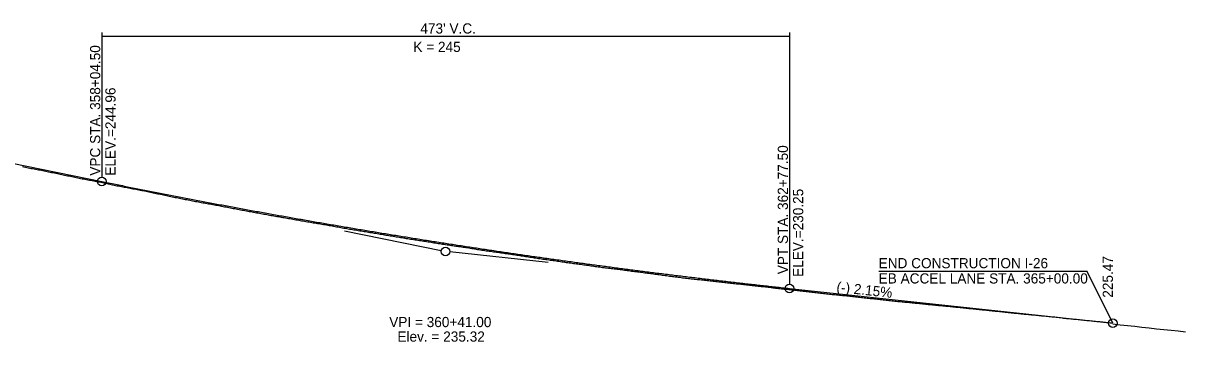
# Model space of a CAD drawing. Extents: x 69 to 2003113, y 512 to 837401.
# Drawn here: x 1914114 to 1914912, y 828577 to 828797 of the extents above; entities that cross this region are included whole.
import ezdxf

# ---------------------------------------------------------------- set-up
doc = ezdxf.new("R2010")
doc.units = 0
for name, color, linetype in [('BR_CENTER LINE BASELINE', 7, 'Continuous'), ('BR_CONCRETE', 7, 'Continuous'), ('BR_GRID DOTS', 7, 'Continuous'), ('BR_GRID LINES', 7, 'Continuous'), ('BR_TEXT', 7, 'Continuous'), ('RD_SHT_IplotShp', 7, 'Continuous')]:
    doc.layers.add(name, color=color, linetype=linetype)

msp = doc.modelspace()

# ---------------------------------------------------------------- linework, layer by layer
at = {"layer": 'BR_CENTER LINE BASELINE'}
for p, q in [((1914334.51, 828653.6), (1914401.14, 828640.02)), ((1914474.68, 828631.84), (1914407.06, 828639.1))]:
    msp.add_line(p, q, dxfattribs=at)
for centre in [(1914404.08, 828639.42), (1914863.08, 828590.15)]:
    msp.add_circle(centre, 3, dxfattribs=at)
at = {"layer": 'BR_GRID DOTS'}
for p, q in [((1914167.58, 828790.11), (1914167.58, 828690.61)), ((1914167.58, 828787.61), (1914640.58, 828787.61)), ((1914640.58, 828790.11), (1914640.58, 828617.03))]:
    msp.add_line(p, q, dxfattribs=at)
msp.add_lwpolyline([(1914863.08, 828590.15), (1914845.48, 828625.75), (1914701.98, 828625.75)], dxfattribs=at)
for centre in [(1914167.58, 828687.61), (1914640.58, 828614.03)]:
    msp.add_circle(centre, 3, dxfattribs=at)
at = {"layer": 'BR_GRID LINES'}
for p, q in [((1913864.58, 828749.35), (1914167.58, 828687.61)), ((1914640.58, 828614.03), (1914863.08, 828590.15))]:
    msp.add_line(p, q, dxfattribs=at)
msp.add_spline([(1914167.58, 828687.61), (1914177.04, 828685.69), (1914186.5, 828683.79), (1914195.96, 828681.91), (1914205.42, 828680.05), (1914214.88, 828678.2), (1914224.34, 828676.37), (1914233.8, 828674.56), (1914243.26, 828672.77), (1914252.72, 828671), (1914262.18, 828669.25), (1914271.64, 828667.51), (1914281.1, 828665.79), (1914290.56, 828664.09), (1914300.02, 828662.41), (1914309.48, 828660.75), (1914318.94, 828659.1), (1914328.4, 828657.48), (1914337.86, 828655.87), (1914347.32, 828654.28), (1914356.78, 828652.71), (1914366.24, 828651.15), (1914375.7, 828649.62), (1914385.16, 828648.1), (1914394.62, 828646.6), (1914404.08, 828645.12), (1914413.54, 828643.66), (1914423, 828642.21), (1914432.46, 828640.79), (1914441.92, 828639.38), (1914451.38, 828637.99), (1914460.84, 828636.62), (1914470.3, 828635.27), (1914479.76, 828633.93), (1914489.22, 828632.62), (1914498.68, 828631.32), (1914508.14, 828630.04), (1914517.6, 828628.78), (1914527.06, 828627.53), (1914536.52, 828626.31), (1914545.98, 828625.1), (1914555.44, 828623.91), (1914564.9, 828622.74), (1914574.36, 828621.59), (1914583.82, 828620.45), (1914593.28, 828619.34), (1914602.74, 828618.24), (1914612.2, 828617.16), (1914621.66, 828616.1), (1914631.12, 828615.06), (1914640.58, 828614.03)], degree=3, dxfattribs=at)
at = {"layer": 'BR_TEXT'}
for points in [[(1914113.08, 828697.81), (1914114.08, 828697.61), (1914115.08, 828697.42), (1914116.08, 828697.23), (1914117.08, 828697.04), (1914118.08, 828696.85), (1914119.08, 828696.66), (1914120.08, 828696.47), (1914121.08, 828696.28), (1914122.08, 828696.09), (1914123.08, 828695.9), (1914124.08, 828695.71), (1914125.08, 828695.52), (1914126.08, 828695.33), (1914127.08, 828695.13), (1914128.08, 828694.93), (1914129.08, 828694.72), (1914130.08, 828694.51), (1914131.08, 828694.31), (1914132.08, 828694.1), (1914133.08, 828693.9), (1914134.08, 828693.69), (1914135.08, 828693.49), (1914136.08, 828693.28), (1914137.08, 828693.07), (1914138.08, 828692.87), (1914139.08, 828692.66), (1914140.08, 828692.45), (1914141.08, 828692.24), (1914142.08, 828692.02), (1914143.08, 828691.81), (1914144.08, 828691.6), (1914145.08, 828691.39), (1914146.08, 828691.18), (1914147.08, 828690.97), (1914148.08, 828690.76), (1914149.08, 828690.54), (1914150.08, 828690.33), (1914151.08, 828690.12), (1914152.08, 828689.92), (1914153.08, 828689.74), (1914154.08, 828689.55), (1914155.08, 828689.36), (1914156.08, 828689.18), (1914157.08, 828688.99), (1914158.08, 828688.8), (1914159.08, 828688.62), (1914160.08, 828688.43), (1914161.08, 828688.25), (1914162.08, 828688.06), (1914163.08, 828687.87)], [(1914163.08, 828687.87), (1914164.08, 828687.68), (1914165.08, 828687.47), (1914166.08, 828687.26), (1914167.08, 828687.04), (1914168.08, 828686.83), (1914169.08, 828686.61), (1914170.08, 828686.4), (1914171.08, 828686.19), (1914172.08, 828685.97), (1914173.08, 828685.76), (1914174.08, 828685.54), (1914175.08, 828685.33), (1914176.08, 828685.12), (1914177.08, 828684.91), (1914178.08, 828684.73), (1914179.08, 828684.54), (1914180.08, 828684.35), (1914181.08, 828684.17), (1914182.08, 828683.98), (1914183.08, 828683.79), (1914184.08, 828683.61), (1914185.08, 828683.42), (1914186.08, 828683.23), (1914187.08, 828683.05), (1914188.08, 828682.86), (1914189.08, 828682.67), (1914190.08, 828682.48), (1914191.08, 828682.29), (1914192.08, 828682.09), (1914193.08, 828681.89), (1914194.08, 828681.7), (1914195.08, 828681.5), (1914196.08, 828681.3), (1914197.08, 828681.11), (1914198.08, 828680.91), (1914199.08, 828680.71), (1914200.08, 828680.52), (1914201.08, 828680.3), (1914202.08, 828680.09), (1914203.08, 828679.87), (1914204.08, 828679.66), (1914205.08, 828679.45), (1914206.08, 828679.23), (1914207.08, 828679.02), (1914208.08, 828678.81), (1914209.08, 828678.6), (1914210.08, 828678.39), (1914211.08, 828678.18), (1914212.08, 828677.97), (1914213.08, 828677.76), (1914214.08, 828677.55), (1914215.08, 828677.34), (1914216.08, 828677.13), (1914217.08, 828676.92), (1914218.08, 828676.71), (1914219.08, 828676.5), (1914220.08, 828676.29), (1914221.08, 828676.1), (1914222.08, 828675.92), (1914223.08, 828675.72), (1914224.08, 828675.52), (1914225.08, 828675.33), (1914226.08, 828675.13), (1914227.08, 828674.93), (1914228.08, 828674.74), (1914229.08, 828674.54), (1914230.08, 828674.35), (1914231.08, 828674.15), (1914232.08, 828673.95), (1914233.08, 828673.75), (1914234.08, 828673.56), (1914235.08, 828673.38), (1914236.08, 828673.21), (1914237.08, 828673.03), (1914238.08, 828672.85), (1914239.08, 828672.67), (1914240.08, 828672.49), (1914241.08, 828672.32), (1914242.08, 828672.14), (1914243.08, 828671.96), (1914244.08, 828671.77), (1914245.08, 828671.58), (1914246.08, 828671.39), (1914247.08, 828671.21), (1914248.08, 828671.02), (1914249.08, 828670.83), (1914250.08, 828670.65), (1914251.08, 828670.46), (1914252.08, 828670.27), (1914253.08, 828670.08), (1914254.08, 828669.9), (1914255.08, 828669.72), (1914256.08, 828669.53), (1914257.08, 828669.34), (1914258.08, 828669.14), (1914259.08, 828668.95), (1914260.08, 828668.75), (1914261.08, 828668.56), (1914262.08, 828668.37), (1914263.08, 828668.17)], [(1914263.08, 828668.17), (1914264.08, 828667.98), (1914265.08, 828667.79), (1914266.08, 828667.61), (1914267.08, 828667.43), (1914268.08, 828667.24), (1914269.08, 828667.06), (1914270.08, 828666.88), (1914271.08, 828666.7), (1914272.08, 828666.52), (1914273.08, 828666.34), (1914274.08, 828666.15), (1914275.08, 828665.97), (1914276.08, 828665.79), (1914277.08, 828665.6), (1914278.08, 828665.41), (1914279.08, 828665.22), (1914280.08, 828665.04), (1914281.08, 828664.86), (1914282.08, 828664.67), (1914283.08, 828664.49), (1914284.08, 828664.3), (1914285.08, 828664.12), (1914286.08, 828663.93), (1914287.08, 828663.76), (1914288.08, 828663.59), (1914289.08, 828663.42), (1914290.08, 828663.24), (1914291.08, 828663.07), (1914292.08, 828662.9), (1914293.08, 828662.73), (1914294.08, 828662.55), (1914295.08, 828662.38), (1914296.08, 828662.21), (1914297.08, 828662.04), (1914298.08, 828661.85), (1914299.08, 828661.66), (1914300.08, 828661.48), (1914301.08, 828661.31), (1914302.08, 828661.14), (1914303.08, 828660.97), (1914304.08, 828660.8), (1914305.08, 828660.63), (1914306.08, 828660.46), (1914307.08, 828660.29), (1914308.08, 828660.12), (1914309.08, 828659.95), (1914310.08, 828659.78), (1914311.08, 828659.62), (1914312.08, 828659.45), (1914313.08, 828659.28), (1914314.08, 828659.12), (1914315.08, 828658.95), (1914316.08, 828658.78), (1914317.08, 828658.62), (1914318.08, 828658.45), (1914319.08, 828658.28), (1914320.08, 828658.12), (1914321.08, 828657.96), (1914322.08, 828657.79), (1914323.08, 828657.61), (1914324.08, 828657.42), (1914325.08, 828657.24), (1914326.08, 828657.05), (1914327.08, 828656.86), (1914328.08, 828656.68), (1914329.08, 828656.49), (1914330.08, 828656.31), (1914331.08, 828656.12), (1914332.08, 828655.94), (1914333.08, 828655.77), (1914334.08, 828655.6), (1914335.08, 828655.43), (1914336.08, 828655.26), (1914337.08, 828655.09), (1914338.08, 828654.92), (1914339.08, 828654.76), (1914340.08, 828654.59), (1914341.08, 828654.42), (1914342.08, 828654.25), (1914343.08, 828654.09), (1914344.08, 828653.93), (1914345.08, 828653.77), (1914346.08, 828653.61), (1914347.08, 828653.44), (1914348.08, 828653.28), (1914349.08, 828653.12), (1914350.08, 828652.95), (1914351.08, 828652.79), (1914352.08, 828652.62), (1914353.08, 828652.46), (1914354.08, 828652.3), (1914355.08, 828652.13), (1914356.08, 828651.96), (1914357.08, 828651.8), (1914358.08, 828651.63), (1914359.08, 828651.46), (1914360.08, 828651.29), (1914361.08, 828651.12), (1914362.08, 828650.95), (1914363.08, 828650.79)], [(1914363.08, 828650.79), (1914364.08, 828650.62), (1914365.08, 828650.45), (1914366.08, 828650.28), (1914367.08, 828650.12), (1914368.08, 828649.96), (1914369.08, 828649.8), (1914370.08, 828649.64), (1914371.08, 828649.48), (1914372.08, 828649.32), (1914373.08, 828649.15), (1914374.08, 828648.99), (1914375.08, 828648.83), (1914376.08, 828648.65), (1914377.08, 828648.5), (1914378.08, 828648.35), (1914379.08, 828648.19), (1914380.08, 828648.04), (1914381.08, 828647.89), (1914382.08, 828647.73), (1914383.08, 828647.58), (1914384.08, 828647.42), (1914385.08, 828647.27), (1914386.08, 828647.12), (1914387.08, 828646.96), (1914388.08, 828646.81), (1914389.08, 828646.65), (1914390.08, 828646.49), (1914391.08, 828646.32), (1914392.08, 828646.16), (1914393.08, 828645.99), (1914394.08, 828645.83), (1914395.08, 828645.66), (1914396.08, 828645.49), (1914397.08, 828645.33), (1914398.08, 828645.16), (1914399.08, 828645.01), (1914400.08, 828644.85), (1914401.08, 828644.7), (1914402.08, 828644.55), (1914403.08, 828644.39), (1914404.08, 828644.24), (1914405.08, 828644.09), (1914406.08, 828643.94), (1914407.08, 828643.78), (1914408.08, 828643.63), (1914409.08, 828643.48), (1914410.08, 828643.34), (1914411.08, 828643.2), (1914412.08, 828643.06), (1914413.08, 828642.92), (1914414.08, 828642.78), (1914415.08, 828642.65), (1914416.08, 828642.51), (1914417.08, 828642.37), (1914418.08, 828642.23), (1914419.08, 828642.09), (1914420.08, 828641.94), (1914421.08, 828641.77), (1914422.08, 828641.6), (1914423.08, 828641.43), (1914424.08, 828641.27), (1914425.08, 828641.1), (1914426.08, 828640.93), (1914427.08, 828640.76), (1914428.08, 828640.59), (1914429.08, 828640.43), (1914430.08, 828640.28), (1914431.08, 828640.14), (1914432.08, 828640), (1914433.08, 828639.87), (1914434.08, 828639.73), (1914435.08, 828639.59), (1914436.08, 828639.45), (1914437.08, 828639.31), (1914438.08, 828639.17), (1914439.08, 828639.03), (1914440.08, 828638.89), (1914441.08, 828638.75), (1914442.08, 828638.6), (1914443.08, 828638.46), (1914444.08, 828638.31), (1914445.08, 828638.17), (1914446.08, 828638.02), (1914447.08, 828637.88), (1914448.08, 828637.74), (1914449.08, 828637.59), (1914450.08, 828637.44), (1914451.08, 828637.29), (1914452.08, 828637.14), (1914453.08, 828636.99), (1914454.08, 828636.84), (1914455.08, 828636.69), (1914456.08, 828636.53), (1914457.08, 828636.38), (1914458.08, 828636.23), (1914459.08, 828636.08), (1914460.08, 828635.93), (1914461.08, 828635.77), (1914462.08, 828635.62), (1914463.08, 828635.46)], [(1914463.08, 828635.46), (1914464.08, 828635.3), (1914465.08, 828635.14), (1914466.08, 828634.98), (1914467.08, 828634.83), (1914468.08, 828634.67), (1914469.08, 828634.52), (1914470.08, 828634.37), (1914471.08, 828634.24), (1914472.08, 828634.1), (1914473.08, 828633.97), (1914474.08, 828633.84), (1914475.08, 828633.7), (1914476.08, 828633.57), (1914477.08, 828633.43), (1914478.08, 828633.3), (1914479.08, 828633.16), (1914480.08, 828633.02), (1914481.08, 828632.88), (1914482.08, 828632.73), (1914483.08, 828632.58), (1914484.08, 828632.43), (1914485.08, 828632.29), (1914486.08, 828632.14), (1914487.08, 828631.99), (1914488.08, 828631.84), (1914489.08, 828631.69), (1914490.08, 828631.55), (1914491.08, 828631.4), (1914492.08, 828631.27), (1914493.08, 828631.14), (1914494.08, 828631.01), (1914495.08, 828630.88), (1914496.08, 828630.75), (1914497.08, 828630.62), (1914498.08, 828630.49), (1914499.08, 828630.36), (1914500.08, 828630.23), (1914501.08, 828630.1), (1914502.08, 828629.96), (1914503.08, 828629.83), (1914504.08, 828629.68), (1914505.08, 828629.53), (1914506.08, 828629.38), (1914507.08, 828629.23), (1914508.08, 828629.08), (1914509.08, 828628.93), (1914510.08, 828628.78), (1914511.08, 828628.65), (1914512.08, 828628.52), (1914513.08, 828628.41), (1914514.08, 828628.3), (1914515.08, 828628.18), (1914516.08, 828628.07), (1914517.08, 828627.96), (1914518.08, 828627.84), (1914519.08, 828627.73), (1914520.08, 828627.62), (1914521.08, 828627.5), (1914522.08, 828627.37), (1914523.08, 828627.23), (1914524.08, 828627.1), (1914525.08, 828626.96), (1914526.08, 828626.83), (1914527.08, 828626.69), (1914528.08, 828626.56), (1914529.08, 828626.42), (1914530.08, 828626.29), (1914531.08, 828626.15), (1914532.08, 828626.02), (1914533.08, 828625.9), (1914534.08, 828625.77), (1914535.08, 828625.64), (1914536.08, 828625.51), (1914537.08, 828625.38), (1914538.08, 828625.26), (1914539.08, 828625.13), (1914540.08, 828625), (1914541.08, 828624.87), (1914542.08, 828624.74), (1914543.08, 828624.61), (1914544.08, 828624.48), (1914545.08, 828624.34), (1914546.08, 828624.21), (1914547.08, 828624.07), (1914548.08, 828623.94), (1914549.08, 828623.81), (1914550.08, 828623.67), (1914551.08, 828623.52), (1914552.08, 828623.39), (1914553.08, 828623.25), (1914554.08, 828623.12), (1914555.08, 828622.98), (1914556.08, 828622.85), (1914557.08, 828622.71), (1914558.08, 828622.58), (1914559.08, 828622.44), (1914560.08, 828622.31), (1914561.08, 828622.17), (1914562.08, 828622.04), (1914563.08, 828621.92)], [(1914563.08, 828621.92), (1914564.08, 828621.8), (1914565.08, 828621.68), (1914566.08, 828621.56), (1914567.08, 828621.44), (1914568.08, 828621.32), (1914569.08, 828621.2), (1914570.08, 828621.09), (1914571.08, 828620.97), (1914572.08, 828620.85), (1914573.08, 828620.73), (1914574.08, 828620.61), (1914575.08, 828620.5), (1914576.08, 828620.4), (1914577.08, 828620.29), (1914578.08, 828620.19), (1914579.08, 828620.08), (1914580.08, 828619.97), (1914581.08, 828619.87), (1914582.08, 828619.76), (1914583.08, 828619.65), (1914584.08, 828619.55), (1914585.08, 828619.44), (1914586.08, 828619.33), (1914587.08, 828619.22), (1914588.08, 828619.09), (1914589.08, 828618.96), (1914590.08, 828618.85), (1914591.08, 828618.74), (1914592.08, 828618.63), (1914593.08, 828618.52), (1914594.08, 828618.41), (1914595.08, 828618.3), (1914596.08, 828618.19), (1914597.08, 828618.08), (1914598.08, 828617.97), (1914599.08, 828617.86), (1914600.08, 828617.75), (1914601.08, 828617.64), (1914602.08, 828617.53), (1914603.08, 828617.42), (1914604.08, 828617.31), (1914605.08, 828617.2), (1914606.08, 828617.09), (1914607.08, 828616.98), (1914608.08, 828616.87), (1914609.08, 828616.76), (1914610.08, 828616.65), (1914611.08, 828616.54), (1914612.08, 828616.43), (1914613.08, 828616.32), (1914614.08, 828616.22), (1914615.08, 828616.11), (1914616.08, 828616), (1914617.08, 828615.9), (1914618.08, 828615.79), (1914619.08, 828615.68), (1914620.08, 828615.57), (1914621.08, 828615.46), (1914622.08, 828615.36), (1914623.08, 828615.25), (1914624.08, 828615.14), (1914625.08, 828615.03), (1914626.08, 828614.92), (1914627.08, 828614.8), (1914628.08, 828614.68), (1914629.08, 828614.54), (1914630.08, 828614.4), (1914631.08, 828614.25), (1914632.08, 828614.12), (1914633.08, 828614.03), (1914634.08, 828613.93), (1914635.08, 828613.83), (1914636.08, 828613.73), (1914637.08, 828613.63), (1914638.08, 828613.53), (1914639.08, 828613.43), (1914640.08, 828613.33), (1914641.08, 828613.22), (1914642.08, 828613.1), (1914643.08, 828612.98), (1914644.08, 828612.86), (1914645.08, 828612.74), (1914646.08, 828612.62), (1914647.08, 828612.51), (1914648.08, 828612.39), (1914649.08, 828612.27), (1914650.08, 828612.16), (1914651.08, 828612.06), (1914652.08, 828611.96), (1914653.08, 828611.86), (1914654.08, 828611.76), (1914655.08, 828611.65), (1914656.08, 828611.55), (1914657.08, 828611.45), (1914658.08, 828611.35), (1914659.08, 828611.24), (1914660.08, 828611.12), (1914661.08, 828611), (1914662.08, 828610.88), (1914663.08, 828610.76)], [(1914663.08, 828610.76), (1914664.08, 828610.64), (1914665.08, 828610.52), (1914666.08, 828610.4), (1914667.08, 828610.29), (1914668.08, 828610.17), (1914669.08, 828610.05), (1914670.08, 828609.94), (1914671.08, 828609.84), (1914672.08, 828609.75), (1914673.08, 828609.66), (1914674.08, 828609.56), (1914675.08, 828609.47), (1914676.08, 828609.38), (1914677.08, 828609.28), (1914678.08, 828609.19), (1914679.08, 828609.1), (1914680.08, 828609.01), (1914681.08, 828608.89), (1914682.08, 828608.77), (1914683.08, 828608.67), (1914684.08, 828608.55), (1914685.08, 828608.44), (1914686.08, 828608.33), (1914687.08, 828608.21), (1914688.08, 828608.1), (1914689.08, 828607.98), (1914690.08, 828607.87), (1914691.08, 828607.76), (1914692.08, 828607.64), (1914693.08, 828607.53), (1914694.08, 828607.42), (1914695.08, 828607.32), (1914696.08, 828607.22), (1914697.08, 828607.12), (1914698.08, 828607.02), (1914699.08, 828606.92), (1914700.08, 828606.82), (1914701.08, 828606.72), (1914702.08, 828606.62), (1914703.08, 828606.52), (1914704.08, 828606.42), (1914705.08, 828606.3), (1914706.08, 828606.18), (1914707.08, 828606.05), (1914708.08, 828605.92), (1914709.08, 828605.8), (1914710.08, 828605.67), (1914711.08, 828605.55), (1914712.08, 828605.44), (1914713.08, 828605.34), (1914714.08, 828605.24), (1914715.08, 828605.15), (1914716.08, 828605.06), (1914717.08, 828604.97), (1914718.08, 828604.87), (1914719.08, 828604.78), (1914720.08, 828604.69), (1914721.08, 828604.6), (1914722.08, 828604.5), (1914723.08, 828604.4), (1914724.08, 828604.3), (1914725.08, 828604.2), (1914726.08, 828604.1), (1914727.08, 828604), (1914728.08, 828603.9), (1914729.08, 828603.8), (1914730.08, 828603.7), (1914731.08, 828603.6), (1914732.08, 828603.5), (1914733.08, 828603.4), (1914734.08, 828603.29), (1914735.08, 828603.19), (1914736.08, 828603.08), (1914737.08, 828602.98), (1914738.08, 828602.88), (1914739.08, 828602.77), (1914740.08, 828602.67), (1914741.08, 828602.56), (1914742.08, 828602.46), (1914743.08, 828602.37), (1914744.08, 828602.28), (1914745.08, 828602.19), (1914746.08, 828602.09), (1914747.08, 828602), (1914748.08, 828601.91), (1914749.08, 828601.82), (1914750.08, 828601.73), (1914751.08, 828601.64), (1914752.08, 828601.55), (1914753.08, 828601.44), (1914754.08, 828601.34), (1914755.08, 828601.24), (1914756.08, 828601.14), (1914757.08, 828601.03), (1914758.08, 828600.93), (1914759.08, 828600.83), (1914760.08, 828600.73), (1914761.08, 828600.63), (1914762.08, 828600.52), (1914763.08, 828600.42)], [(1914763.08, 828600.42), (1914764.08, 828600.32), (1914765.08, 828600.22), (1914766.08, 828600.12), (1914767.08, 828600.02), (1914768.08, 828599.92), (1914769.08, 828599.82), (1914770.08, 828599.72), (1914771.08, 828599.62), (1914772.08, 828599.52), (1914773.08, 828599.42), (1914774.08, 828599.32), (1914775.08, 828599.22), (1914776.08, 828599.11), (1914777.08, 828599.01), (1914778.08, 828598.91), (1914779.08, 828598.8), (1914780.08, 828598.7), (1914781.08, 828598.6), (1914782.08, 828598.5), (1914783.08, 828598.4), (1914784.08, 828598.29), (1914785.08, 828598.19), (1914786.08, 828598.09), (1914787.08, 828597.99), (1914788.08, 828597.89), (1914789.08, 828597.77), (1914790.08, 828597.66), (1914791.08, 828597.54), (1914792.08, 828597.42), (1914793.08, 828597.31), (1914794.08, 828597.2), (1914795.08, 828597.11), (1914796.08, 828597.01), (1914797.08, 828596.91), (1914798.08, 828596.82), (1914799.08, 828596.72), (1914800.08, 828596.63), (1914801.08, 828596.53), (1914802.08, 828596.43), (1914803.08, 828596.34), (1914804.08, 828596.24), (1914805.08, 828596.15), (1914806.08, 828596.05), (1914807.08, 828595.96), (1914808.08, 828595.86), (1914809.08, 828595.77), (1914810.08, 828595.67), (1914811.08, 828595.57), (1914812.08, 828595.48), (1914813.08, 828595.38), (1914814.08, 828595.29), (1914815.08, 828595.19), (1914816.08, 828595.09), (1914817.08, 828594.99), (1914818.08, 828594.9), (1914819.08, 828594.8), (1914820.08, 828594.7), (1914821.08, 828594.6), (1914822.08, 828594.51), (1914823.08, 828594.41), (1914824.08, 828594.31), (1914825.08, 828594.19), (1914826.08, 828594.07), (1914827.08, 828593.94), (1914828.08, 828593.82), (1914829.08, 828593.69), (1914830.08, 828593.57), (1914831.08, 828593.46), (1914832.08, 828593.37), (1914833.08, 828593.27), (1914834.08, 828593.17), (1914835.08, 828593.07), (1914836.08, 828592.97), (1914837.08, 828592.88), (1914838.08, 828592.78), (1914839.08, 828592.68), (1914840.08, 828592.58), (1914841.08, 828592.49), (1914842.08, 828592.39), (1914843.08, 828592.28), (1914844.08, 828592.18), (1914845.08, 828592.07), (1914846.08, 828591.97), (1914847.08, 828591.86), (1914848.08, 828591.75), (1914849.08, 828591.65), (1914850.08, 828591.56), (1914851.08, 828591.47), (1914852.08, 828591.37), (1914853.08, 828591.28), (1914854.08, 828591.19), (1914855.08, 828591.1), (1914856.08, 828591), (1914857.08, 828590.89), (1914858.08, 828590.77), (1914859.08, 828590.64), (1914860.08, 828590.52), (1914861.08, 828590.4), (1914862.08, 828590.27), (1914863.08, 828590.15)], [(1914863.08, 828589.59), (1914868.08, 828589.1), (1914873.08, 828588.58), (1914878.08, 828588.03), (1914883.08, 828587.47), (1914888.08, 828586.89), (1914893.08, 828586.3), (1914898.08, 828585.8), (1914903.08, 828585.3), (1914908.08, 828584.77), (1914913.08, 828584.27)]]:
    msp.add_lwpolyline(points, dxfattribs=at)

# ---------------------------------------------------------------- texts
at = {"layer": 'BR_CENTER LINE BASELINE'}
msp.add_text('(-) 2.15%', height=7, rotation=353.87332, dxfattribs=at).set_placement((1914672.7, 828611.63))
at = {"layer": 'BR_CONCRETE'}
for s, p in [('VPC STA. 358+04.50 ', (1914166.58, 828691.63)), ('ELEV.=244.96', (1914177.08, 828691.63)), ('VPT STA. 362+77.50 ', (1914639.58, 828623.81)), ('ELEV.=230.25', (1914650.08, 828621.97))]:
    msp.add_text(s, height=7, rotation=90, dxfattribs=at).set_placement(p)
at = {"layer": 'BR_GRID DOTS'}
for s, p in [("473' V.C.", (1914386.76, 828789.41)), ('K = 245', (1914381.95, 828776.74))]:
    msp.add_text(s, height=7, dxfattribs=at).set_placement(p)
at = {"layer": 'RD_SHT_IplotShp'}
for s, p in [('END CONSTRUCTION I-26 ', (1914701.98, 828627.92)), ('EB ACCEL LANE STA. 365+00.00', (1914701.98, 828617.42)), ('VPI = 360+41.00', (1914365.34, 828587.42)), ('Elev. = 235.32', (1914370.99, 828577.42))]:
    msp.add_text(s, height=7, dxfattribs=at).set_placement(p)
msp.add_text('225.47', height=7, rotation=90, dxfattribs=at).set_placement((1914863.08, 828607.65))

doc.saveas('drawing.dxf')
